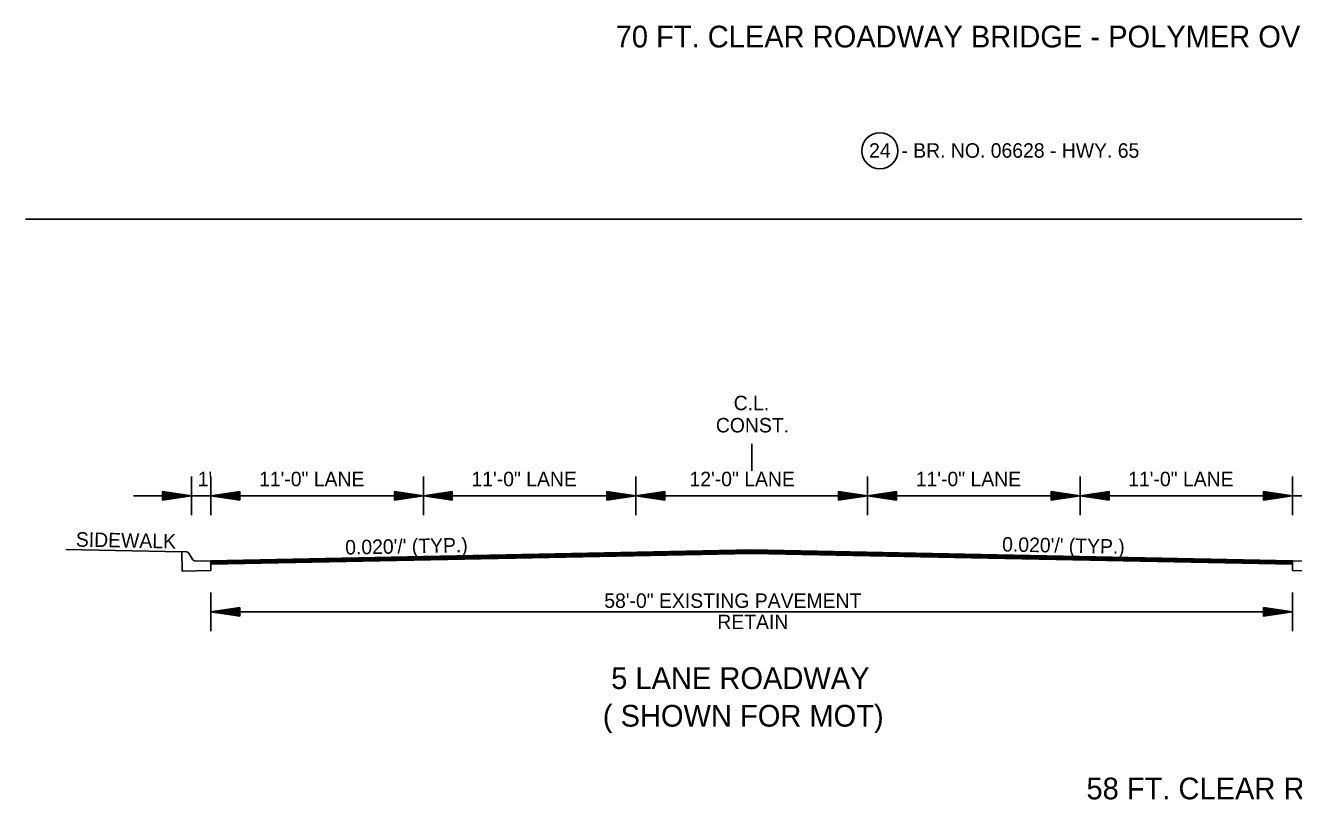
# Model space of a CAD drawing. Extents: x 550980 to 1930787, y -1972975 to 596640.
# Drawn here: x 551006 to 551662, y -1957794 to -1957393 of the extents above; entities that cross this region are included whole.
import ezdxf

# ---------------------------------------------------------------- set-up
doc = ezdxf.new("R2010")
doc.units = 0
doc.layers.add('R_Border', color=7, linetype='Continuous')
doc.layers.add('R_Draft', color=7, linetype='Continuous')

msp = doc.modelspace()

# ---------------------------------------------------------------- linework, layer by layer
at = {"layer": 'R_Border'}
for p, q in [((551005.61, -1957493.51), (552066.88, -1957493.51)), ((551381.65, -1957609.84), (551381.65, -1957623.84)), ((551091.65, -1957626.84), (551091.65, -1957646.84)), ((551101.65, -1957626.84), (551101.65, -1957646.84)), ((551211.65, -1957626.84), (551211.65, -1957646.84)), ((551321.65, -1957626.84), (551321.65, -1957646.84)), ((551441.65, -1957626.84), (551441.65, -1957646.84)), ((551551.65, -1957626.84), (551551.65, -1957646.84)), ((551661.65, -1957626.84), (551661.65, -1957646.84)), ((551061.65, -1957636.84), (551701.65, -1957636.84)), ((551076.65, -1957634.59), (551091.65, -1957636.84)), ((551076.65, -1957634.59), (551076.65, -1957639.09)), ((551076.65, -1957634.97), (551089.14, -1957636.84)), ((551076.65, -1957635.35), (551086.56, -1957636.84)), ((551076.65, -1957635.72), (551084.07, -1957636.84)), ((551076.65, -1957636.11), (551081.52, -1957636.84)), ((551076.65, -1957636.49), (551079.02, -1957636.84)), ((551076.65, -1957639.09), (551091.65, -1957636.84)), ((551076.65, -1957637.58), (551081.52, -1957636.84)), ((551076.65, -1957638.33), (551086.56, -1957636.84)), ((551076.65, -1957638.72), (551089.14, -1957636.84)), ((551076.65, -1957637.96), (551084.07, -1957636.84)), ((551076.65, -1957637.19), (551079.02, -1957636.84)), ((551116.65, -1957634.59), (551101.65, -1957636.84)), ((551116.65, -1957639.09), (551101.65, -1957636.84)), ((551116.65, -1957634.97), (551104.15, -1957636.84)), ((551116.65, -1957638.72), (551104.15, -1957636.84)), ((551116.65, -1957635.35), (551106.73, -1957636.84)), ((551116.65, -1957638.33), (551106.73, -1957636.84)), ((551116.65, -1957635.72), (551109.23, -1957636.84)), ((551116.65, -1957637.96), (551109.23, -1957636.84)), ((551116.65, -1957636.11), (551111.77, -1957636.84)), ((551116.65, -1957637.57), (551111.77, -1957636.84)), ((551116.65, -1957636.49), (551114.28, -1957636.84)), ((551116.65, -1957637.19), (551114.28, -1957636.84)), ((551116.65, -1957639.09), (551116.65, -1957634.59)), ((551196.65, -1957634.59), (551211.65, -1957636.84)), ((551196.65, -1957634.59), (551196.65, -1957639.09)), ((551196.65, -1957634.97), (551209.14, -1957636.84)), ((551196.65, -1957635.35), (551206.56, -1957636.84)), ((551196.65, -1957635.72), (551204.07, -1957636.84)), ((551196.65, -1957636.11), (551201.52, -1957636.84)), ((551196.65, -1957636.49), (551199.02, -1957636.84)), ((551196.65, -1957639.09), (551211.65, -1957636.84)), ((551196.65, -1957637.58), (551201.52, -1957636.84)), ((551196.65, -1957638.33), (551206.56, -1957636.84)), ((551196.65, -1957638.72), (551209.14, -1957636.84)), ((551196.65, -1957637.96), (551204.07, -1957636.84)), ((551196.65, -1957637.19), (551199.02, -1957636.84)), ((551226.65, -1957634.59), (551211.65, -1957636.84)), ((551226.65, -1957639.09), (551211.65, -1957636.84)), ((551226.65, -1957634.97), (551214.15, -1957636.84)), ((551226.65, -1957638.72), (551214.15, -1957636.84)), ((551226.65, -1957635.35), (551216.73, -1957636.84)), ((551226.65, -1957638.33), (551216.73, -1957636.84)), ((551226.65, -1957635.72), (551219.23, -1957636.84)), ((551226.65, -1957637.96), (551219.23, -1957636.84)), ((551226.65, -1957636.11), (551221.77, -1957636.84)), ((551226.65, -1957637.57), (551221.77, -1957636.84)), ((551226.65, -1957636.49), (551224.28, -1957636.84)), ((551226.65, -1957637.19), (551224.28, -1957636.84)), ((551226.65, -1957639.09), (551226.65, -1957634.59)), ((551306.65, -1957634.59), (551321.65, -1957636.84)), ((551306.65, -1957634.59), (551306.65, -1957639.09)), ((551306.65, -1957634.97), (551319.14, -1957636.84)), ((551306.65, -1957635.35), (551316.56, -1957636.84)), ((551306.65, -1957635.72), (551314.07, -1957636.84)), ((551306.65, -1957636.11), (551311.52, -1957636.84)), ((551306.65, -1957636.49), (551309.02, -1957636.84)), ((551306.65, -1957639.09), (551321.65, -1957636.84)), ((551306.65, -1957637.58), (551311.52, -1957636.84)), ((551306.65, -1957638.33), (551316.56, -1957636.84)), ((551306.65, -1957638.72), (551319.14, -1957636.84)), ((551306.65, -1957637.96), (551314.07, -1957636.84)), ((551306.65, -1957637.19), (551309.02, -1957636.84)), ((551336.65, -1957634.59), (551321.65, -1957636.84)), ((551336.65, -1957639.09), (551321.65, -1957636.84)), ((551336.65, -1957634.97), (551324.15, -1957636.84)), ((551336.65, -1957638.72), (551324.15, -1957636.84)), ((551336.65, -1957635.35), (551326.73, -1957636.84)), ((551336.65, -1957638.33), (551326.73, -1957636.84)), ((551336.65, -1957635.72), (551329.23, -1957636.84)), ((551336.65, -1957637.96), (551329.23, -1957636.84)), ((551336.65, -1957636.11), (551331.77, -1957636.84)), ((551336.65, -1957637.57), (551331.77, -1957636.84)), ((551336.65, -1957636.49), (551334.28, -1957636.84)), ((551336.65, -1957637.19), (551334.28, -1957636.84)), ((551336.65, -1957639.09), (551336.65, -1957634.59)), ((551426.65, -1957634.59), (551441.65, -1957636.84)), ((551426.65, -1957634.59), (551426.65, -1957639.09)), ((551426.65, -1957634.97), (551439.14, -1957636.84)), ((551426.65, -1957635.35), (551436.56, -1957636.84)), ((551426.65, -1957635.72), (551434.07, -1957636.84)), ((551426.65, -1957636.11), (551431.52, -1957636.84)), ((551426.65, -1957636.49), (551429.02, -1957636.84)), ((551426.65, -1957639.09), (551441.65, -1957636.84)), ((551426.65, -1957637.58), (551431.52, -1957636.84)), ((551426.65, -1957638.33), (551436.56, -1957636.84)), ((551426.65, -1957638.72), (551439.14, -1957636.84)), ((551426.65, -1957637.96), (551434.07, -1957636.84)), ((551426.65, -1957637.19), (551429.02, -1957636.84)), ((551456.65, -1957634.59), (551441.65, -1957636.84)), ((551456.65, -1957639.09), (551441.65, -1957636.84)), ((551456.65, -1957634.97), (551444.15, -1957636.84)), ((551456.65, -1957638.72), (551444.15, -1957636.84)), ((551456.65, -1957635.35), (551446.73, -1957636.84)), ((551456.65, -1957638.33), (551446.73, -1957636.84)), ((551456.65, -1957635.72), (551449.23, -1957636.84)), ((551456.65, -1957637.96), (551449.23, -1957636.84)), ((551456.65, -1957636.11), (551451.77, -1957636.84)), ((551456.65, -1957637.57), (551451.77, -1957636.84)), ((551456.65, -1957636.49), (551454.28, -1957636.84)), ((551456.65, -1957637.19), (551454.28, -1957636.84)), ((551456.65, -1957639.09), (551456.65, -1957634.59)), ((551536.65, -1957634.59), (551551.65, -1957636.84)), ((551536.65, -1957634.59), (551536.65, -1957639.09)), ((551536.65, -1957634.97), (551549.14, -1957636.84)), ((551536.65, -1957635.35), (551546.56, -1957636.84)), ((551536.65, -1957635.72), (551544.07, -1957636.84)), ((551536.65, -1957636.11), (551541.52, -1957636.84)), ((551536.65, -1957636.49), (551539.02, -1957636.84)), ((551536.65, -1957639.09), (551551.65, -1957636.84)), ((551536.65, -1957637.58), (551541.52, -1957636.84)), ((551536.65, -1957638.33), (551546.56, -1957636.84)), ((551536.65, -1957638.72), (551549.14, -1957636.84)), ((551536.65, -1957637.96), (551544.07, -1957636.84)), ((551536.65, -1957637.19), (551539.02, -1957636.84)), ((551566.65, -1957634.59), (551551.65, -1957636.84)), ((551566.65, -1957639.09), (551551.65, -1957636.84)), ((551566.65, -1957634.97), (551554.15, -1957636.84)), ((551566.65, -1957638.72), (551554.15, -1957636.84)), ((551566.65, -1957635.35), (551556.73, -1957636.84)), ((551566.65, -1957638.33), (551556.73, -1957636.84)), ((551566.65, -1957635.72), (551559.23, -1957636.84)), ((551566.65, -1957637.96), (551559.23, -1957636.84)), ((551566.65, -1957636.11), (551561.77, -1957636.84)), ((551566.65, -1957637.57), (551561.77, -1957636.84)), ((551566.65, -1957636.49), (551564.28, -1957636.84)), ((551566.65, -1957637.19), (551564.28, -1957636.84)), ((551566.65, -1957639.09), (551566.65, -1957634.59)), ((551646.65, -1957634.59), (551661.65, -1957636.84)), ((551646.65, -1957634.59), (551646.65, -1957639.09)), ((551646.65, -1957634.97), (551659.14, -1957636.84)), ((551646.65, -1957635.35), (551656.56, -1957636.84)), ((551646.65, -1957635.72), (551654.07, -1957636.84)), ((551646.65, -1957636.11), (551651.52, -1957636.84)), ((551646.65, -1957636.49), (551649.02, -1957636.84)), ((551646.65, -1957639.09), (551661.65, -1957636.84)), ((551646.65, -1957637.58), (551651.52, -1957636.84)), ((551646.65, -1957638.33), (551656.56, -1957636.84)), ((551646.65, -1957638.72), (551659.14, -1957636.84)), ((551646.65, -1957637.96), (551654.07, -1957636.84)), ((551646.65, -1957637.19), (551649.02, -1957636.84)), ((551086.55, -1957665.74), (551026.55, -1957664.54)), ((551101.65, -1957686.84), (551101.65, -1957706.84)), ((551661.65, -1957686.84), (551661.65, -1957706.84)), ((551116.65, -1957694.59), (551101.65, -1957696.84)), ((551101.65, -1957696.84), (551661.65, -1957696.84)), ((551116.65, -1957699.09), (551101.65, -1957696.84)), ((551116.65, -1957694.97), (551104.15, -1957696.84)), ((551116.65, -1957698.72), (551104.15, -1957696.84)), ((551116.65, -1957695.35), (551106.73, -1957696.84)), ((551116.65, -1957698.33), (551106.73, -1957696.84)), ((551116.65, -1957695.72), (551109.23, -1957696.84)), ((551116.65, -1957697.96), (551109.23, -1957696.84)), ((551116.65, -1957696.11), (551111.77, -1957696.84)), ((551116.65, -1957697.57), (551111.77, -1957696.84)), ((551116.65, -1957696.49), (551114.28, -1957696.84)), ((551116.65, -1957697.19), (551114.28, -1957696.84)), ((551116.65, -1957699.09), (551116.65, -1957694.59)), ((551646.65, -1957694.59), (551661.65, -1957696.84)), ((551646.65, -1957694.59), (551646.65, -1957699.09)), ((551646.65, -1957694.97), (551659.14, -1957696.84)), ((551646.65, -1957695.35), (551656.56, -1957696.84)), ((551646.65, -1957695.72), (551654.07, -1957696.84)), ((551646.65, -1957696.11), (551651.52, -1957696.84)), ((551646.65, -1957696.49), (551649.02, -1957696.84)), ((551646.65, -1957699.09), (551661.65, -1957696.84)), ((551646.65, -1957697.58), (551651.52, -1957696.84)), ((551646.65, -1957698.33), (551656.56, -1957696.84)), ((551646.65, -1957698.72), (551659.14, -1957696.84)), ((551646.65, -1957697.96), (551654.07, -1957696.84)), ((551646.65, -1957697.19), (551649.02, -1957696.84))]:
    msp.add_line(p, q, dxfattribs=at)
for points in [[(551101.65, -1957670.44), (551381.65, -1957664.84), (551661.65, -1957670.44)], [(551101.65, -1957670.74), (551381.65, -1957665.14), (551661.65, -1957670.74)], [(551101.65, -1957671.04), (551381.65, -1957665.44), (551661.65, -1957671.04)], [(551101.65, -1957671.34), (551381.65, -1957665.74), (551661.65, -1957671.34)], [(551101.65, -1957671.64), (551381.65, -1957666.04), (551661.65, -1957671.64)], [(551101.65, -1957671.94), (551381.65, -1957666.34), (551661.65, -1957671.94)], [(551101.65, -1957672.24), (551381.65, -1957666.64), (551661.65, -1957672.24)]]:
    msp.add_lwpolyline(points, dxfattribs=at)
msp.add_circle((551448.03, -1957458.11), 9.34, dxfattribs=at)
at = {"layer": 'R_Draft'}
for p, q in [((551088.29, -1957665.71), (551086.55, -1957665.74)), ((551090.48, -1957666.92), (551091.96, -1957669.38)), ((551094.15, -1957670.59), (551101.65, -1957670.44)), ((551669.15, -1957670.59), (551661.65, -1957670.44))]:
    msp.add_line(p, q, dxfattribs=at)
for points in [[(551086.55, -1957665.74), (551086.75, -1957675.74), (551101.65, -1957675.44), (551101.65, -1957670.44)], [(551676.74, -1957665.74), (551676.54, -1957675.74), (551661.65, -1957675.44), (551661.65, -1957670.44)]]:
    msp.add_lwpolyline(points, dxfattribs=at)
for centre, start, end in [((551088.34, -1957668.21), 30.94405, 91.14576), ((551094.1, -1957668.09), 210.94405, 271.14576)]:
    msp.add_arc(centre, 2.5, start, end, dxfattribs=at)

# ---------------------------------------------------------------- texts
at = {"layer": 'R_Border'}
for s, height, p in [('C.L.', 7.5, (551372.32, -1957592.49)), ('CONST.', 7.5, (551363.1, -1957603.99)), ("1'", 7.5, (551094.82, -1957631.84)), ('11\'-0" LANE', 7.5, (551126.59, -1957631.84)), ('11\'-0" LANE', 7.5, (551236.59, -1957631.84)), ('12\'-0" LANE', 7.5, (551349.46, -1957631.84)), ('11\'-0" LANE', 7.5, (551466.59, -1957631.84)), ('11\'-0" LANE', 7.5, (551576.59, -1957631.84)), ('58\'-0" EXISTING PAVEMENT', 7.5, (551305.32, -1957694.84)), ('RETAIN', 7.5, (551363.84, -1957705.84)), ('5 LANE ROADWAY', 11.25, (551308.92, -1957736.84)), ('( SHOWN FOR MOT)', 11.25, (551304.58, -1957756.32)), ('58 FT. CLEAR ROADWAY BRIDGE - POLYMER OVERLAY', 11.25, (551554.97, -1957793.97))]:
    msp.add_text(s, height=height, dxfattribs=at).set_placement(p)
for s, rotation, p in [('SIDEWALK', 358.8542, (551031.69, -1957663.09)), ("0.020'/' (TYP.)", 1.1458, (551171.26, -1957667.25)), ("0.020'/' (TYP.)", 358.8542, (551511.26, -1957665.63))]:
    msp.add_text(s, height=7.5, rotation=rotation, dxfattribs=at).set_placement(p)
at = {"layer": 'R_Draft'}
for s, height, p in [('70 FT. CLEAR ROADWAY BRIDGE - POLYMER OVERLAY', 11.25, (551311.24, -1957404.62)), ('24  - BR. NO. 06628 - HWY. 65', 7.5, (551442.42, -1957461.74))]:
    msp.add_text(s, height=height, dxfattribs=at).set_placement(p)

doc.saveas('drawing.dxf')
